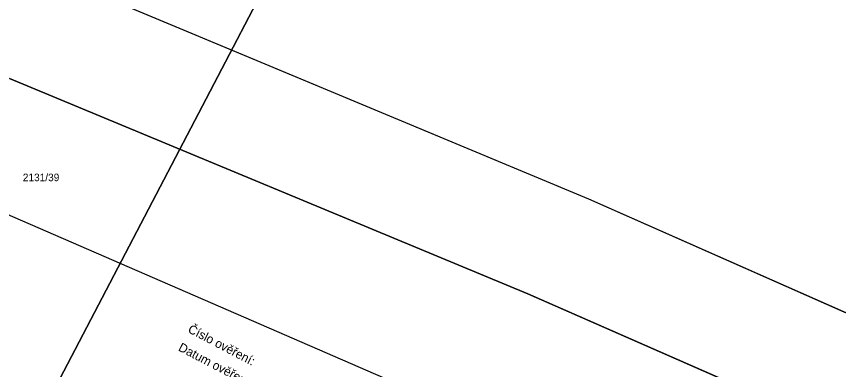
# Model space of a CAD drawing. Extents: x -866656 to -858817, y -1041816 to -1038653.
# Drawn here: x -860687.2 to -860502.2, y -1040332.3 to -1040252.9 of the extents above; entities that cross this region are included whole.
import ezdxf

# ---------------------------------------------------------------- set-up
doc = ezdxf.new("R2010")
doc.units = 0
for name, color, linetype in [('Hranice parcel', 7, 'Continuous'), ('Parcelní čísla', 7, 'Continuous'), ('SZDC', 7, 'Continuous'), ('tisk ramy', 7, 'Continuous'), ('Vrstva 53', 7, 'Continuous')]:
    doc.layers.add(name, color=color, linetype=linetype)

msp = doc.modelspace()

# ---------------------------------------------------------------- linework, layer by layer
at = {"layer": 'Hranice parcel'}
for p, q in [((-860685.09, -1040241.12), (-860558.47, -1040293.91)), ((-860688.72, -1040266.91), (-860572.09, -1040315.32)), ((-860567.23, -1040350.35), (-860700.32, -1040292.62)), ((-860558.47, -1040293.91), (-860442.88, -1040345.07)), ((-860572.09, -1040315.32), (-860480.84, -1040355.3))]:
    msp.add_line(p, q, dxfattribs=at)
at = {"layer": 'SZDC'}
for points in [[(-861261.75, -1039976.4), (-861207.66, -1040016.44), (-861178.07, -1040032.92), (-861123.93, -1040056.86), (-861120.81, -1040053.41), (-861111.29, -1040057.53), (-861106.75, -1040059.49), (-861091.91, -1040065.91), (-861080.02, -1040037.82), (-861096.96, -1040029.84), (-861063.4, -1040039.15), (-861045.83, -1040048.83), (-861015.69, -1040065.42), (-860995.26, -1040081.93), (-860925.73, -1040118.15), (-860902.64, -1040130.18), (-860914.76, -1040137.1), (-860798.14, -1040185.35), (-860681.52, -1040233.61), (-860685.09, -1040241.12), (-860558.47, -1040293.91), (-860442.88, -1040345.07), (-860431.3, -1040350.27), (-860382.79, -1040375.51)], [(-860374.99, -1040397.25), (-860480.84, -1040355.3), (-860572.09, -1040315.32), (-860688.72, -1040266.91)]]:
    msp.add_lwpolyline(points, dxfattribs=at)
at = {"layer": 'tisk ramy'}
for points in [[(-861617.95, -1039899.29), (-860700.91, -1040379.13), (-860572.48, -1040133.7), (-861489.53, -1039653.85)], [(-861489.53, -1039653.85), (-860572.48, -1040133.7), (-860700.91, -1040379.13), (-861617.95, -1039899.29)]]:
    msp.add_lwpolyline(points, close=True, dxfattribs=at)
at = {"layer": 'Vrstva 53'}
for points in [[(-861261.75, -1039976.4), (-861207.66, -1040016.44), (-861178.07, -1040032.92), (-861123.93, -1040056.86), (-861120.81, -1040053.41), (-861111.29, -1040057.53), (-861106.75, -1040059.49), (-861091.91, -1040065.91), (-861080.02, -1040037.82), (-861096.96, -1040029.84), (-861063.4, -1040039.15), (-861045.83, -1040048.83), (-861015.69, -1040065.42), (-860995.26, -1040081.93), (-860925.73, -1040118.15), (-860902.64, -1040130.18), (-860914.76, -1040137.1), (-860798.14, -1040185.35), (-860681.52, -1040233.61), (-860685.09, -1040241.12), (-860558.47, -1040293.91), (-860442.88, -1040345.07), (-860431.3, -1040350.27), (-860382.79, -1040375.51)], [(-860374.99, -1040397.25), (-860480.84, -1040355.3), (-860572.09, -1040315.32), (-860688.72, -1040266.91)]]:
    msp.add_lwpolyline(points, dxfattribs=at)

# ---------------------------------------------------------------- texts
at = {"layer": 'Parcelní čísla'}
msp.add_text('2131/39', height=1.7, dxfattribs=at).set_placement((-860685.74, -1040289.98))
at = {"layer": 'tisk ramy'}
for s, p in [('Číslo ověření:', (-860648.77, -1040323.86)), ('Datum ověření:', (-860650.92, -1040327.97))]:
    msp.add_text(s, height=2, rotation=332.3792, dxfattribs=at).set_placement(p)

doc.saveas('drawing.dxf')
